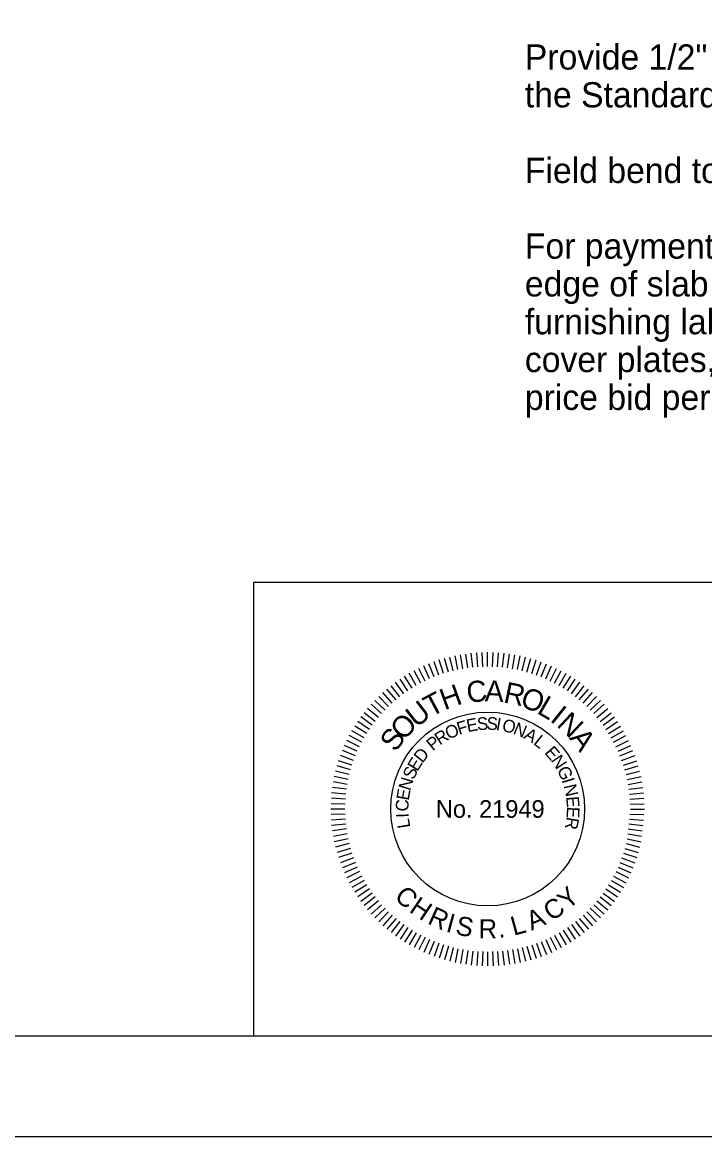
# Model space of a CAD drawing. Extents: x 3.7 to 39.9, y -2.3 to 19.7.
# Drawn here: x 28.28 to 31.66, y -2.32 to 3.21 of the extents above; entities that cross this region are included whole.
import ezdxf

# ---------------------------------------------------------------- set-up
doc = ezdxf.new("R2010")
doc.units = 0
for name, color, linetype in [('BR_BORDER LINES', 7, 'Continuous'), ('BR_DETAILS', 7, 'Continuous'), ('BR_TEXT', 7, 'Continuous'), ('RD_SHT_IplotShp', 7, 'Continuous')]:
    doc.layers.add(name, color=color, linetype=linetype)

msp = doc.modelspace()

# ---------------------------------------------------------------- linework, layer by layer
at = {"layer": 'BR_BORDER LINES'}
for p, q in [((29.4239, 0.433), (31.7364, 0.433)), ((29.4239, -1.8171), (29.4239, 0.433)), ((5.5698, -1.817), (39.2364, -1.817)), ((3.7365, -2.3155), (39.7365, -2.3155))]:
    msp.add_line(p, q, dxfattribs=at)
at = {"layer": 'BR_DETAILS'}
for p, q in [((30.4121, -0.0071), (30.3952, 0.0607)), ((30.4121, -0.0071), (30.3952, 0.0607)), ((30.436, -0.0007), (30.4215, 0.0677)), ((30.436, -0.0007), (30.4215, 0.0677)), ((30.4604, 0.0032), (30.4483, 0.0719)), ((30.4604, 0.0032), (30.4483, 0.0719)), ((30.4848, 0.007), (30.475, 0.0762)), ((30.4848, 0.007), (30.475, 0.0762)), ((30.5092, 0.0109), (30.5019, 0.0804)), ((30.5092, 0.0109), (30.5019, 0.0804)), ((30.5338, 0.0122), (30.529, 0.0818)), ((30.5338, 0.0122), (30.529, 0.0818)), ((30.5585, 0.0135), (30.556, 0.0832)), ((30.5585, 0.0135), (30.556, 0.0832)), ((30.5831, 0.0148), (30.5831, 0.0847)), ((30.5831, 0.0148), (30.5831, 0.0847)), ((30.6078, 0.0135), (30.6102, 0.0832)), ((30.6078, 0.0135), (30.6102, 0.0832)), ((30.6324, 0.0122), (30.6373, 0.0818)), ((30.6324, 0.0122), (30.6373, 0.0818)), ((30.6571, 0.0109), (30.6644, 0.0804)), ((30.6571, 0.0109), (30.6644, 0.0804)), ((30.6815, 0.007), (30.6912, 0.0762)), ((30.6815, 0.007), (30.6912, 0.0762)), ((30.7059, 0.0032), (30.718, 0.0719)), ((30.7059, 0.0032), (30.718, 0.0719)), ((30.7303, -0.0007), (30.7448, 0.0677)), ((30.7303, -0.0007), (30.7448, 0.0677)), ((30.7303, -0.0007), (30.7448, 0.0677)), ((30.7541, -0.0071), (30.771, 0.0607)), ((30.7541, -0.0071), (30.771, 0.0607)), ((30.7541, -0.0071), (30.771, 0.0607)), ((30.2733, -0.0576), (30.2427, 0.0051)), ((30.2733, -0.0576), (30.2427, 0.0051)), ((30.2953, -0.0464), (30.2669, 0.0174)), ((30.2953, -0.0464), (30.2669, 0.0174)), ((30.3183, -0.0376), (30.2922, 0.0272)), ((30.3183, -0.0376), (30.2922, 0.0272)), ((30.3414, -0.0287), (30.3175, 0.0369)), ((30.3414, -0.0287), (30.3175, 0.0369)), ((30.3644, -0.0199), (30.3428, 0.0466)), ((30.3644, -0.0199), (30.3428, 0.0466)), ((30.3883, -0.0135), (30.3691, 0.0536)), ((30.3883, -0.0135), (30.3691, 0.0536)), ((30.778, -0.0135), (30.7972, 0.0536)), ((30.778, -0.0135), (30.7972, 0.0536)), ((30.778, -0.0135), (30.7972, 0.0536)), ((30.8018, -0.0199), (30.8234, 0.0466)), ((30.8018, -0.0199), (30.8234, 0.0466)), ((30.8018, -0.0199), (30.8234, 0.0466)), ((30.8249, -0.0287), (30.8488, 0.0369)), ((30.8249, -0.0287), (30.8488, 0.0369)), ((30.8249, -0.0287), (30.8488, 0.0369)), ((30.8479, -0.0376), (30.8741, 0.0272)), ((30.8479, -0.0376), (30.8741, 0.0272)), ((30.8479, -0.0376), (30.8741, 0.0272)), ((30.871, -0.0464), (30.8994, 0.0174)), ((30.871, -0.0464), (30.8994, 0.0174)), ((30.871, -0.0464), (30.8994, 0.0174)), ((30.893, -0.0576), (30.9236, 0.0051)), ((30.893, -0.0576), (30.9236, 0.0051)), ((30.893, -0.0576), (30.9236, 0.0051)), ((30.1879, -0.1069), (30.1488, -0.0491)), ((30.1879, -0.1069), (30.1488, -0.0491)), ((30.2086, -0.0935), (30.1716, -0.0343)), ((30.2086, -0.0935), (30.1716, -0.0343)), ((30.2293, -0.08), (30.1943, -0.0195)), ((30.2293, -0.08), (30.1943, -0.0195)), ((30.2513, -0.0688), (30.2185, -0.0072)), ((30.2513, -0.0688), (30.2185, -0.0072)), ((30.915, -0.0688), (30.9477, -0.0072)), ((30.915, -0.0688), (30.9477, -0.0072)), ((30.915, -0.0688), (30.9477, -0.0072)), ((30.937, -0.08), (30.9719, -0.0195)), ((30.937, -0.08), (30.9719, -0.0195)), ((30.937, -0.08), (30.9719, -0.0195)), ((30.9577, -0.0935), (30.9947, -0.0343)), ((30.9577, -0.0935), (30.9947, -0.0343)), ((30.9577, -0.0935), (30.9947, -0.0343)), ((30.9784, -0.1069), (31.0174, -0.0491)), ((30.9784, -0.1069), (31.0174, -0.0491)), ((30.9784, -0.1069), (31.0174, -0.0491)), ((30.1288, -0.1515), (30.0839, -0.098)), ((30.1288, -0.1515), (30.0839, -0.098)), ((30.148, -0.1359), (30.105, -0.0809)), ((30.148, -0.1359), (30.105, -0.0809)), ((30.1672, -0.1204), (30.1261, -0.0638)), ((30.1672, -0.1204), (30.1261, -0.0638)), ((30.9991, -0.1204), (31.0402, -0.0638)), ((30.9991, -0.1204), (31.0402, -0.0638)), ((30.9991, -0.1204), (31.0402, -0.0638)), ((31.0183, -0.1359), (31.0613, -0.0809)), ((31.0183, -0.1359), (31.0613, -0.0809)), ((31.0183, -0.1359), (31.0613, -0.0809)), ((31.0375, -0.1515), (31.0824, -0.098)), ((31.0375, -0.1515), (31.0824, -0.098)), ((31.0375, -0.1515), (31.0824, -0.098)), ((30.0747, -0.2019), (30.0245, -0.1534)), ((30.0747, -0.2019), (30.0245, -0.1534)), ((30.0921, -0.1845), (30.0436, -0.1343)), ((30.0921, -0.1845), (30.0436, -0.1343)), ((30.1096, -0.167), (30.0628, -0.1151)), ((30.1096, -0.167), (30.0628, -0.1151)), ((31.0567, -0.167), (31.1034, -0.1151)), ((31.0567, -0.167), (31.1034, -0.1151)), ((31.0567, -0.167), (31.1034, -0.1151)), ((31.0741, -0.1845), (31.1226, -0.1343)), ((31.0741, -0.1845), (31.1226, -0.1343)), ((31.0741, -0.1845), (31.1226, -0.1343)), ((31.0916, -0.2019), (31.1418, -0.1534)), ((31.0916, -0.2019), (31.1418, -0.1534)), ((31.0916, -0.2019), (31.1418, -0.1534)), ((30.0261, -0.2578), (29.9711, -0.2148)), ((30.0261, -0.2578), (29.9711, -0.2148)), ((30.0417, -0.2386), (29.9882, -0.1937)), ((30.0417, -0.2386), (29.9882, -0.1937)), ((30.0572, -0.2194), (30.0053, -0.1726)), ((30.0572, -0.2194), (30.0053, -0.1726)), ((31.1091, -0.2194), (31.161, -0.1726)), ((31.1091, -0.2194), (31.161, -0.1726)), ((31.1091, -0.2194), (31.161, -0.1726)), ((31.1246, -0.2386), (31.1781, -0.1937)), ((31.1246, -0.2386), (31.1781, -0.1937)), ((31.1246, -0.2386), (31.1781, -0.1937)), ((31.1401, -0.2578), (31.1951, -0.2148)), ((31.1401, -0.2578), (31.1951, -0.2148)), ((31.1401, -0.2578), (31.1951, -0.2148)), ((29.9971, -0.2977), (29.9393, -0.2586)), ((29.9971, -0.2977), (29.9393, -0.2586)), ((30.0106, -0.277), (29.954, -0.2359)), ((30.0106, -0.277), (29.954, -0.2359)), ((31.1557, -0.277), (31.2122, -0.2359)), ((31.1557, -0.277), (31.2122, -0.2359)), ((31.1557, -0.277), (31.2122, -0.2359)), ((31.1691, -0.2977), (31.227, -0.2586)), ((31.1691, -0.2977), (31.227, -0.2586)), ((31.1691, -0.2977), (31.227, -0.2586)), ((29.959, -0.3611), (29.8974, -0.3283)), ((29.959, -0.3611), (29.8974, -0.3283)), ((29.9702, -0.3391), (29.9097, -0.3041)), ((29.9702, -0.3391), (29.9097, -0.3041)), ((29.9837, -0.3184), (29.9245, -0.2814)), ((29.9837, -0.3184), (29.9245, -0.2814)), ((31.1826, -0.3184), (31.2418, -0.2814)), ((31.1826, -0.3184), (31.2418, -0.2814)), ((31.1826, -0.3184), (31.2418, -0.2814)), ((31.196, -0.3391), (31.2566, -0.3041)), ((31.196, -0.3391), (31.2566, -0.3041)), ((31.196, -0.3391), (31.2566, -0.3041)), ((31.2072, -0.3611), (31.2689, -0.3283)), ((31.2072, -0.3611), (31.2689, -0.3283)), ((31.2072, -0.3611), (31.2689, -0.3283)), ((29.9366, -0.4051), (29.8728, -0.3767)), ((29.9366, -0.4051), (29.8728, -0.3767)), ((29.9478, -0.3831), (29.8851, -0.3525)), ((29.9478, -0.3831), (29.8851, -0.3525)), ((31.2184, -0.3831), (31.2812, -0.3525)), ((31.2184, -0.3831), (31.2812, -0.3525)), ((31.2184, -0.3831), (31.2812, -0.3525)), ((31.2297, -0.4051), (31.2935, -0.3767)), ((31.2297, -0.4051), (31.2935, -0.3767)), ((31.2297, -0.4051), (31.2935, -0.3767)), ((29.9189, -0.4512), (29.8533, -0.4273)), ((29.9189, -0.4512), (29.8533, -0.4273)), ((29.9278, -0.4281), (29.863, -0.402)), ((29.9278, -0.4281), (29.863, -0.402)), ((31.2385, -0.4281), (31.3032, -0.402)), ((31.2385, -0.4281), (31.3032, -0.402)), ((31.2385, -0.4281), (31.3032, -0.402)), ((31.2473, -0.4512), (31.3129, -0.4273)), ((31.2473, -0.4512), (31.3129, -0.4273)), ((31.2473, -0.4512), (31.3129, -0.4273)), ((29.9037, -0.4981), (29.8366, -0.4789)), ((29.9037, -0.4981), (29.8366, -0.4789)), ((29.9101, -0.4742), (29.8436, -0.4526)), ((29.9101, -0.4742), (29.8436, -0.4526)), ((31.2562, -0.4742), (31.3227, -0.4526)), ((31.2562, -0.4742), (31.3227, -0.4526)), ((31.2562, -0.4742), (31.3227, -0.4526)), ((31.2626, -0.4981), (31.3297, -0.4789)), ((31.2626, -0.4981), (31.3297, -0.4789)), ((31.2626, -0.4981), (31.3297, -0.4789)), ((29.8909, -0.5458), (29.8225, -0.5313)), ((29.8909, -0.5458), (29.8225, -0.5313)), ((29.8973, -0.5219), (29.8296, -0.505)), ((29.8973, -0.5219), (29.8296, -0.505)), ((31.269, -0.5219), (31.3367, -0.505)), ((31.269, -0.5219), (31.3367, -0.505)), ((31.269, -0.5219), (31.3367, -0.505)), ((31.2754, -0.5458), (31.3437, -0.5313)), ((31.2754, -0.5458), (31.3437, -0.5313)), ((31.2754, -0.5458), (31.3437, -0.5313)), ((29.8832, -0.5946), (29.814, -0.5848)), ((29.8832, -0.5946), (29.814, -0.5848)), ((29.887, -0.5702), (29.8183, -0.5581)), ((29.887, -0.5702), (29.8183, -0.5581)), ((31.2792, -0.5702), (31.348, -0.5581)), ((31.2792, -0.5702), (31.348, -0.5581)), ((31.2792, -0.5702), (31.348, -0.5581)), ((31.2831, -0.5946), (31.3522, -0.5848)), ((31.2831, -0.5946), (31.3522, -0.5848)), ((31.2831, -0.5946), (31.3522, -0.5848)), ((29.878, -0.6436), (29.8084, -0.6388)), ((29.878, -0.6436), (29.8084, -0.6388)), ((29.8793, -0.619), (29.8098, -0.6116)), ((29.8793, -0.619), (29.8098, -0.6116)), ((31.287, -0.619), (31.3565, -0.6116)), ((31.287, -0.619), (31.3565, -0.6116)), ((31.287, -0.619), (31.3565, -0.6116)), ((31.2883, -0.6436), (31.3579, -0.6388)), ((31.2883, -0.6436), (31.3579, -0.6388)), ((31.2883, -0.6436), (31.3579, -0.6388)), ((29.8754, -0.6929), (29.8055, -0.6929)), ((29.8754, -0.6929), (29.8055, -0.6929)), ((29.8767, -0.6683), (29.807, -0.6658)), ((29.8767, -0.6683), (29.807, -0.6658)), ((29.8767, -0.7176), (29.807, -0.72)), ((29.8767, -0.7176), (29.807, -0.72)), ((31.2882, -0.7176), (31.3579, -0.72)), ((31.2882, -0.7176), (31.3579, -0.72)), ((31.2895, -0.6683), (31.3593, -0.6658)), ((31.2895, -0.6683), (31.3593, -0.6658)), ((31.2895, -0.6683), (31.3593, -0.6658)), ((31.2908, -0.6929), (31.3607, -0.6929)), ((31.2908, -0.6929), (31.3607, -0.6929)), ((31.2908, -0.6929), (31.3607, -0.6929)), ((29.878, -0.7422), (29.8084, -0.7471)), ((29.878, -0.7422), (29.8084, -0.7471)), ((29.8793, -0.7669), (29.8098, -0.7742)), ((29.8793, -0.7669), (29.8098, -0.7742)), ((31.2831, -0.7665), (31.3522, -0.7738)), ((31.2831, -0.7665), (31.3522, -0.7738)), ((31.2857, -0.7421), (31.3551, -0.7469)), ((31.2857, -0.7421), (31.3551, -0.7469)), ((29.8832, -0.7913), (29.814, -0.801)), ((29.8832, -0.7913), (29.814, -0.801)), ((29.887, -0.8157), (29.8183, -0.8278)), ((29.887, -0.8157), (29.8183, -0.8278)), ((31.278, -0.8154), (31.3466, -0.8275)), ((31.278, -0.8154), (31.3466, -0.8275)), ((31.2805, -0.7909), (31.3494, -0.8006)), ((31.2805, -0.7909), (31.3494, -0.8006)), ((29.8909, -0.8401), (29.8225, -0.8546)), ((29.8909, -0.8401), (29.8225, -0.8546)), ((29.8973, -0.8639), (29.8296, -0.8808)), ((29.8973, -0.8639), (29.8296, -0.8808)), ((31.269, -0.8639), (31.3367, -0.8808)), ((31.269, -0.8639), (31.3367, -0.8808)), ((31.2754, -0.8401), (31.3437, -0.8546)), ((31.2754, -0.8401), (31.3437, -0.8546)), ((29.9037, -0.8878), (29.8366, -0.907)), ((29.9037, -0.8878), (29.8366, -0.907)), ((29.9101, -0.9116), (29.8436, -0.9332)), ((29.9189, -0.9347), (29.8533, -0.9586)), ((29.9189, -0.9347), (29.8533, -0.9586)), ((31.2473, -0.9347), (31.3129, -0.9586)), ((31.2473, -0.9347), (31.3129, -0.9586)), ((31.2562, -0.9116), (31.3227, -0.9332)), ((31.2562, -0.9116), (31.3227, -0.9332)), ((31.2626, -0.8878), (31.3297, -0.907)), ((31.2626, -0.8878), (31.3297, -0.907)), ((29.9278, -0.9577), (29.863, -0.9839)), ((29.9278, -0.9577), (29.863, -0.9839)), ((29.9366, -0.9808), (29.8728, -1.0092)), ((29.9366, -0.9808), (29.8728, -1.0092)), ((31.2297, -0.9808), (31.2935, -1.0092)), ((31.2297, -0.9808), (31.2935, -1.0092)), ((31.2385, -0.9577), (31.3032, -0.9839)), ((31.2385, -0.9577), (31.3032, -0.9839)), ((29.9478, -1.0028), (29.8851, -1.0334)), ((29.9478, -1.0028), (29.8851, -1.0334)), ((29.959, -1.0248), (29.8974, -1.0575)), ((29.959, -1.0248), (29.8974, -1.0575)), ((29.9702, -1.0468), (29.9097, -1.0817)), ((29.9702, -1.0468), (29.9097, -1.0817)), ((31.196, -1.0468), (31.2566, -1.0817)), ((31.196, -1.0468), (31.2566, -1.0817)), ((31.2072, -1.0248), (31.2689, -1.0575)), ((31.2072, -1.0248), (31.2689, -1.0575)), ((31.2184, -1.0028), (31.2812, -1.0334)), ((31.2184, -1.0028), (31.2812, -1.0334)), ((29.9837, -1.0675), (29.9245, -1.1045)), ((29.9837, -1.0675), (29.9245, -1.1045)), ((29.9971, -1.0882), (29.9393, -1.1272)), ((29.9971, -1.0882), (29.9393, -1.1272)), ((31.1691, -1.0882), (31.227, -1.1272)), ((31.1691, -1.0882), (31.227, -1.1272)), ((31.1826, -1.0675), (31.2418, -1.1045)), ((31.1826, -1.0675), (31.2418, -1.1045)), ((30.0106, -1.1089), (29.954, -1.15)), ((30.0106, -1.1089), (29.954, -1.15)), ((30.0261, -1.1281), (29.9711, -1.1711)), ((30.0261, -1.1281), (29.9711, -1.1711)), ((30.0417, -1.1473), (29.9882, -1.1922)), ((30.0417, -1.1473), (29.9882, -1.1922)), ((31.1246, -1.1473), (31.1781, -1.1922)), ((31.1246, -1.1473), (31.1781, -1.1922)), ((31.1401, -1.1281), (31.1951, -1.1711)), ((31.1401, -1.1281), (31.1951, -1.1711)), ((31.1557, -1.1089), (31.2122, -1.15)), ((31.1557, -1.1089), (31.2122, -1.15)), ((30.0572, -1.1665), (30.0053, -1.2132)), ((30.0572, -1.1665), (30.0053, -1.2132)), ((30.0747, -1.1839), (30.0245, -1.2324)), ((30.0747, -1.1839), (30.0245, -1.2324)), ((30.0921, -1.2014), (30.0436, -1.2516)), ((30.0921, -1.2014), (30.0436, -1.2516)), ((31.0741, -1.2014), (31.1226, -1.2516)), ((31.0741, -1.2014), (31.1226, -1.2516)), ((31.0916, -1.1839), (31.1418, -1.2324)), ((31.0916, -1.1839), (31.1418, -1.2324)), ((31.1091, -1.1665), (31.161, -1.2132)), ((31.1091, -1.1665), (31.161, -1.2132)), ((30.1096, -1.2189), (30.0628, -1.2708)), ((30.1096, -1.2189), (30.0628, -1.2708)), ((30.1288, -1.2344), (30.0839, -1.2879)), ((30.1288, -1.2344), (30.0839, -1.2879)), ((30.148, -1.2499), (30.105, -1.3049)), ((30.148, -1.2499), (30.105, -1.3049)), ((30.1672, -1.2655), (30.1261, -1.322)), ((30.1672, -1.2655), (30.1261, -1.322)), ((30.9991, -1.2655), (31.0402, -1.322)), ((30.9991, -1.2655), (31.0402, -1.322)), ((31.0183, -1.2499), (31.0613, -1.3049)), ((31.0183, -1.2499), (31.0613, -1.3049)), ((31.0375, -1.2344), (31.0824, -1.2879)), ((31.0375, -1.2344), (31.0824, -1.2879)), ((31.0567, -1.2189), (31.1034, -1.2708)), ((30.1879, -1.2789), (30.1488, -1.3368)), ((30.1879, -1.2789), (30.1488, -1.3368)), ((30.2086, -1.2924), (30.1716, -1.3516)), ((30.2086, -1.2924), (30.1716, -1.3516)), ((30.2293, -1.3058), (30.1943, -1.3664)), ((30.2293, -1.3058), (30.1943, -1.3664)), ((30.2513, -1.317), (30.2185, -1.3787)), ((30.2513, -1.317), (30.2185, -1.3787)), ((30.915, -1.317), (30.9477, -1.3787)), ((30.915, -1.317), (30.9477, -1.3787)), ((30.937, -1.3058), (30.9719, -1.3664)), ((30.937, -1.3058), (30.9719, -1.3664)), ((30.9577, -1.2924), (30.9947, -1.3516)), ((30.9577, -1.2924), (30.9947, -1.3516)), ((30.9784, -1.2789), (31.0174, -1.3368)), ((30.9784, -1.2789), (31.0174, -1.3368)), ((30.2733, -1.3282), (30.2427, -1.391)), ((30.2733, -1.3282), (30.2427, -1.391)), ((30.2953, -1.3394), (30.2669, -1.4033)), ((30.2953, -1.3394), (30.2669, -1.4033)), ((30.3183, -1.3483), (30.2922, -1.413)), ((30.3183, -1.3483), (30.2922, -1.413)), ((30.3414, -1.3571), (30.3175, -1.4227)), ((30.3414, -1.3571), (30.3175, -1.4227)), ((30.3644, -1.366), (30.3428, -1.4325)), ((30.3644, -1.366), (30.3428, -1.4325)), ((30.3883, -1.3724), (30.3691, -1.4395)), ((30.3883, -1.3724), (30.3691, -1.4395)), ((30.4121, -1.3788), (30.3952, -1.4465)), ((30.4121, -1.3788), (30.3952, -1.4465)), ((30.7541, -1.3788), (30.771, -1.4465)), ((30.7541, -1.3788), (30.771, -1.4465)), ((30.778, -1.3724), (30.7972, -1.4395)), ((30.778, -1.3724), (30.7972, -1.4395)), ((30.8018, -1.366), (30.8234, -1.4325)), ((30.8018, -1.366), (30.8234, -1.4325)), ((30.8249, -1.3571), (30.8488, -1.4227)), ((30.8249, -1.3571), (30.8488, -1.4227)), ((30.8479, -1.3483), (30.8741, -1.413)), ((30.8479, -1.3483), (30.8741, -1.413)), ((30.871, -1.3394), (30.8994, -1.4033)), ((30.871, -1.3394), (30.8994, -1.4033)), ((30.893, -1.3282), (30.9236, -1.391)), ((30.893, -1.3282), (30.9236, -1.391)), ((30.436, -1.3852), (30.4215, -1.4535)), ((30.436, -1.3852), (30.4215, -1.4535)), ((30.4604, -1.389), (30.4483, -1.4578)), ((30.4604, -1.389), (30.4483, -1.4578)), ((30.4848, -1.3929), (30.475, -1.462)), ((30.4848, -1.3929), (30.475, -1.462)), ((30.5092, -1.3968), (30.5019, -1.4663)), ((30.5092, -1.3968), (30.5019, -1.4663)), ((30.5338, -1.398), (30.529, -1.4677)), ((30.5338, -1.398), (30.529, -1.4677)), ((30.5585, -1.3993), (30.556, -1.4691)), ((30.5585, -1.3993), (30.556, -1.4691)), ((30.5831, -1.4006), (30.5831, -1.4705)), ((30.5831, -1.4006), (30.5831, -1.4705)), ((30.6078, -1.3993), (30.6102, -1.4691)), ((30.6078, -1.3993), (30.6102, -1.4691)), ((30.6324, -1.398), (30.6373, -1.4677)), ((30.6324, -1.398), (30.6373, -1.4677)), ((30.6571, -1.3968), (30.6644, -1.4663)), ((30.6571, -1.3968), (30.6644, -1.4663)), ((30.6815, -1.3929), (30.6912, -1.462)), ((30.6815, -1.3929), (30.6912, -1.462)), ((30.7059, -1.389), (30.718, -1.4578)), ((30.7059, -1.389), (30.718, -1.4578)), ((30.7303, -1.3852), (30.7448, -1.4535)), ((30.7303, -1.3852), (30.7448, -1.4535))]:
    msp.add_line(p, q, dxfattribs=at)
msp.add_circle((30.5831, -0.692), 0.4805, dxfattribs=at)
at = {"layer": 'RD_SHT_IplotShp'}
msp.add_lwpolyline([(3.7365, 19.6831), (39.7365, 19.6831), (39.7365, -2.3169), (3.7365, -2.3169)], close=True, dxfattribs=at)

# ---------------------------------------------------------------- texts
at = {"layer": 'BR_DETAILS'}
for s, height, rotation, p in [('C', 0.1048, 6.8832, (30.4848, -0.1671)), ('A', 0.1048, 357.9448, (30.5676, -0.1582)), ('T', 0.1048, 28.0947, (30.3016, -0.2382)), ('H', 0.1048, 19.9102, (30.369, -0.2027)), ('R', 0.1048, 348.267, (30.6576, -0.1632)), ('O', 0.1048, 339.3286, (30.7388, -0.1812)), ('U', 0.1048, 37.7726, (30.2293, -0.292)), ('L', 0.1048, 329.6507, (30.8225, -0.2146)), ('I', 0.1048, 321.4663, (30.888, -0.2535)), ('N', 0.1048, 317.0007, (30.9213, -0.2786)), ('O', 0.1048, 47.4504, (30.1671, -0.3572)), ('O', 0.0628, 25.285, (30.3899, -0.3491)), ('F', 0.0628, 17.0454, (30.4411, -0.325)), ('E', 0.0628, 10.5018, (30.4838, -0.3112)), ('S', 0.0628, 3.4002, (30.5317, -0.3018)), ('S', 0.0628, 356.8566, (30.5765, -0.2985)), ('I', 0.0628, 350.313, (30.6214, -0.3003)), ('O', 0.0628, 346.0455, (30.6504, -0.3042)), ('N', 0.0628, 337.8059, (30.7053, -0.3179)), ('S', 0.1048, 54.9027, (30.1271, -0.414)), ('R', 0.0628, 32.9611, (30.3459, -0.378)), ('A', 0.0628, 329.5663, (30.7577, -0.3393)), ('L', 0.0628, 321.3267, (30.8064, -0.3679)), ('A', 0.1048, 307.3229, (30.9859, -0.3413)), ('P', 0.0628, 39.5047, (30.3116, -0.4071)), ('E', 0.0628, 310.8083, (30.8618, -0.4141)), ('E', 0.0628, 58.2627, (30.2344, -0.5095)), ('D', 0.0628, 51.1611, (30.2596, -0.4678)), ('N', 0.0628, 303.7068, (30.8941, -0.4507)), ('S', 0.0628, 64.8063, (30.2159, -0.5505)), ('G', 0.0628, 295.4672, (30.9254, -0.4978)), ('N', 0.0628, 73.0458, (30.1994, -0.6046)), ('I', 0.0628, 287.2276, (30.9497, -0.5488)), ('E', 0.0628, 80.1474, (30.1915, -0.6527)), ('N', 0.0628, 282.96, (30.9594, -0.5765)), ('C', 0.0628, 87.8235, (30.1898, -0.7053)), ('E', 0.0628, 274.7205, (30.9721, -0.6316)), ('E', 0.0628, 267.6189, (30.9765, -0.6802)), ('I', 0.0628, 92.0911, (30.1918, -0.7346)), ('L', 0.0628, 99.1926, (30.2001, -0.7826)), ('R', 0.0628, 260.5173, (30.975, -0.7289)), ('C', 0.0942, 317.0914, (30.1157, -1.1324)), ('Y', 0.0942, 42.1707, (30.9818, -1.1955)), ('H', 0.0942, 326.011, (30.1897, -1.1995)), ('C', 0.0942, 33.2512, (30.8989, -1.2512)), ('R', 0.0942, 335.6684, (30.2804, -1.2584)), ('I', 0.0942, 344.5879, (30.3718, -1.2985)), ('A', 0.0942, 23.5938, (30.8006, -1.2963)), ('S', 0.0942, 349.0441, (30.4196, -1.313)), ('R', 0.0942, 359.8228, (30.5386, -1.3327)), ('L', 0.0942, 15.4265, (30.7126, -1.321)), ('.', 0.0942, 8.7423, (30.6385, -1.3318))]:
    msp.add_text(s, height=height, rotation=rotation, dxfattribs=at).set_placement(p)
msp.add_text('No. 21949', height=0.08737, dxfattribs=at).set_placement((30.3265, -0.7357))
at = {"layer": 'BR_TEXT'}
for s, p in [('Provide 1/2" Dia. headed studs that meet the requirements of Section 709 of', (30.7676, 2.9739)), ('the Standard Specifications. Electrically weld all studs.', (30.7676, 2.7864)), ('Field bend top slab reinforcing as required to clear anchor studs.', (30.7676, 2.4114)), ('For payment purposes, measure along the centerline of the joint from the', (30.7676, 2.0364)), ('edge of slab to the edge of slab. Include all costs associated with', (30.7676, 1.8489)), ('furnishing labor, materials, fabrication, and installation of armor plates,', (30.7676, 1.6614)), ('cover plates, and seals complete and in place in the unit', (30.7676, 1.4739)), ('price bid per linear foot of Compression Seal Joint.', (30.7676, 1.2864))]:
    msp.add_text(s, height=0.125, dxfattribs=at).set_placement(p)

doc.saveas('drawing.dxf')
